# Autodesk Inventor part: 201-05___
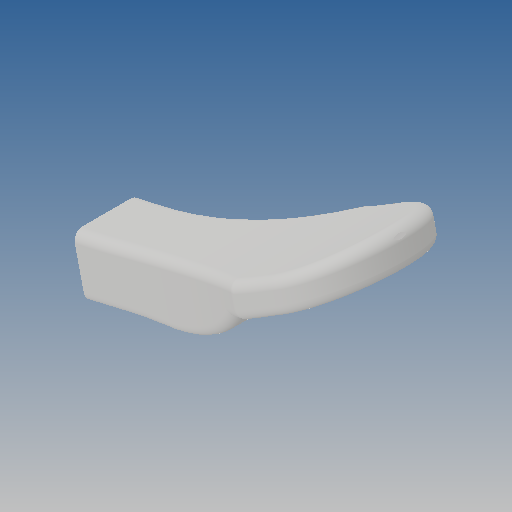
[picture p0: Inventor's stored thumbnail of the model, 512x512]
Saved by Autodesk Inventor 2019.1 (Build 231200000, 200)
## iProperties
Created: 2010-06
Part Number: 201-05___
Material: Ogólny
Document SubType Name: Modeling
Designer: CADENGINEERING4
Density: 1 g/cm^3
Appearance: Domyślna
Author: CADENGINEERING4
Revision Number: ANY
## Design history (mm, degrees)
feature "NONE"
node "Bryła1"
